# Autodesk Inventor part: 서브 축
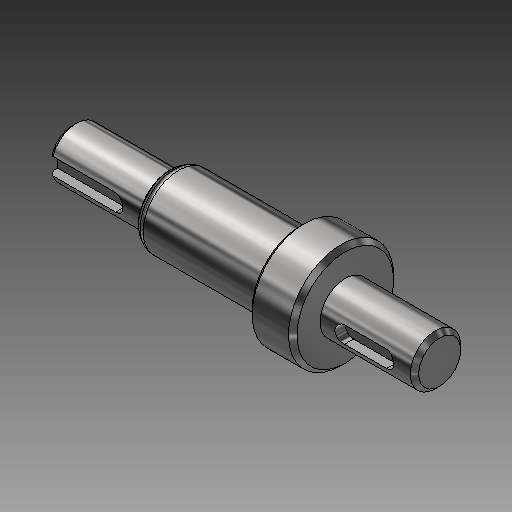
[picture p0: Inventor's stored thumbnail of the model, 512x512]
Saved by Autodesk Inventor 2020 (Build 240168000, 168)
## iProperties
Created: 2016-04
Part Number: 서브 축
Document SubType Name: Modeling
Designer: mdu
Density: 1 g/cm^3
Mass: 19.9624 g
Surface Area: 57.7178 cm^2
Volume: 19.9624 cm^3
Material: 강철, 연강
Appearance: 반광택
Author: mdu
Revision Number: 1
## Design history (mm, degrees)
sketch "스케치1"
  geometry: L1 (-16.331, 0)-(-103.831, 0); L2 (-16.331, 0)-(-16.331, -6); L3 (-16.331, -6)-(-38.831, -6); L4 (-38.831, -12.5)-(-46.5, -12.5); L5 (-46.5, -8.5)-(-79.013, -8.5); L6 (-103.831, -6)-(-103.831, 0); L7 (-46.5, -8.5)-(-46.5, -12.5); L8 (-38.831, -6)-(-38.831, -12.5); L9 (-46.5, 12.249)-(-46.5, -12.249) reference; L10 (-38.831, -17)-(-38.831, 17) reference; L11 (-103.831, -6)-(-80.831, -6); L12 (-80.831, -6)-(-80.831, -7.45); L13 (-80.831, -7.45)-(-79.013, -8.5); 2 further points
  constraints: 23 end point, 6 perpendicular, 2 collinear, 2 parallel, 1 horizontal, 1 midpoint, 1 point on line
  dimensions: "d1" = 12 diameter of L3 L1; "d2" = 25 diameter of L4 L1; "d3" = 17 diameter of L5 L1; "d18" = 22.5 distance of L2.end L3.end; "d20" = 65 distance between parallel lines of L6 L8; "d21" = 7.66872 distance of L4.start L4.end (derived); "d28" = 12 diameter of L11 L1; "d29" = 23 distance of L6.start L11.end; "d30" = 14.9 diameter of L12.end L1; "d32" = 30 deg angle of L5 L13
revolve "회전1" sketch "스케치1" stored, may be unused: angle "d5" = 90 deg
chamfer "모따기1" distance "d6" = 1; stored, may be unused: second distance "d7" = 2, angle "d8" = 45 deg
node "작업 평면1"
sketch "스케치2"
  geometry: L1 (11.25, 5)-(11.25, -5) reference; L2 (-5.75, -2)-(4.25, -2); L3 (4.25, 2)-(-5.75, 2); A1 r 2 centre (4.25, 0) between (4.25, -2) and (4.25, 2); A2 r 2 centre (-5.75, 0) between (-5.75, 2) and (-5.75, -2); 2 further points
  constraints: 4 end point, 4 point on circle, 4 tangent, 2 centre point, 1 horizontal alignment, 1 midpoint, 1 parallel, 1 perpendicular
  dimensions: "d9" = 4 distance between parallel lines of L2 L3; "d10" = 14 dimension on A1 A2; "d11" = 5 distance edge to line of A1 L1
extrude "돌출1" cut sketch "스케치2" distance "d12" = 2.5; taper "d13" = 0 deg
node "작업 평면2"
sketch "스케치3"
  geometry: L1 (-103.831, -5)-(-103.831, 5) reference; L2 (-103.831, 2)-(-87.831, 2); L3 (-87.831, -2)-(-103.831, -2); A1 r 2 centre (-87.831, 0) between (-87.831, -2) and (-87.831, 2); 2 further points
  constraints: 4 end point, 2 perpendicular, 2 point on circle, 2 point on line, 2 tangent, 1 centre point, 1 horizontal alignment, 1 midpoint
  dimensions: "d14" = 4 distance between parallel lines of L3 L2; "d15" = 18 dimension on A1 L1
extrude "돌출2" cut sketch "스케치3" distance "d16" = 2.5; taper "d17" = 0 deg
sketch "스케치4"
  geometry: C1 r 12.5 at (0, 0) reference; 1 further point
extrude "돌출3" join sketch "스케치4" distance "d22" = 3; taper "d23" = 0 deg
chamfer "모따기2" distance "d24" = 1; stored, may be unused: second distance "d25" = 2, angle "d26" = 45 deg
fillet "모깎기1" dims "d34" = 1
fillet "모깎기2" dims "d35" = 2
node "솔리드1"
node "참조4"
node "참조5"
other parameters: "d33" = 6
